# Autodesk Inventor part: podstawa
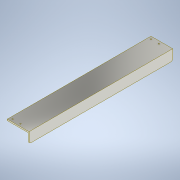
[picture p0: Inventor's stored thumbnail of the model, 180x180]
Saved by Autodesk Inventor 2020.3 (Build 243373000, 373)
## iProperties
Created: 2021-01
Part Number: podstawa
Material: Ogólny
Document SubType Name: Modeling
Designer: Dom
Density: 1 g/cm^3
Appearance: Domyślna
Author: Dom
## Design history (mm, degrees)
sketch "Szkic1"
  geometry: L1 (82.5, 545)-(-82.5, 545); L2 (-82.5, 545)-(-82.5, -545); L3 (-82.5, -545)-(82.5, -545); L4 (82.5, -545)-(82.5, 545); L5 (82.5, 545)-(-82.5, -545); L6 (-82.5, 545)-(82.5, -545); 1 further point
  constraints: 12 end point, 2 midpoint, 2 parallel, 1 horizontal, 1 perpendicular
  dimensions: "d0" = 165 distance of L3.end L2.end; "d1" = 1090 distance of L2.end L1.end
extrude "Wyciągnięcie proste1" new body sketch "Szkic1" distance "d2" = 10; taper "d3" = 0 deg
sketch "Szkic3"
  geometry: L1 (-82.5, 545)-(82.5, 545) reference; L2 (82.5, -545)-(-82.5, -545) reference; L3 (82.5, 545)-(77.5, 545); L4 (77.5, 545)-(77.5, -545); L5 (77.5, -545)-(82.5, -545); L6 (82.5, -545)-(82.5, 545); 3 further points
  constraints: 8 end point, 2 parallel, 1 horizontal, 1 perpendicular, 1 point on line
  dimensions: "d11" = 5 distance between parallel lines of L6 L4
extrude "Wyciągnięcie proste3" join sketch "Szkic3" distance "d12" = 70; taper "d13" = 0 deg
sketch "Szkic4"
  geometry: L1 (-82.5, -545)-(-82.5, 545) reference; L2 (77.5, -545)-(-82.5, -545) reference; 3 further points
  constraints: 1 horizontal alignment
  dimensions: "d21" = 20 distance from line of point (-62.5, -525) L1; "d22" = 20 distance from line of point (-62.5, -525) L2; "d23" = 60 distance of point (-2.5, -525) point (-62.5, -525)
hole "Otwór1" sketch "Szkic4" at (-62.5, -525), (-2.5, -525) diameter "d14" = 8.376; stored, may be unused: countersink angle "d18" = 90 deg, drill point angle "d20" = 118 deg; dims "d15" = 20, "d16" = 11, "d17" = 2, "d19" = 27.3
chamfer "Faza2" distance "d24" = 10; stored, may be unused: second distance "d25" = 2, angle "d26" = 45 deg
mirror "Odbij1"
node "Bryła1"
